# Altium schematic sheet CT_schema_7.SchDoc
size 277 x 170 mm
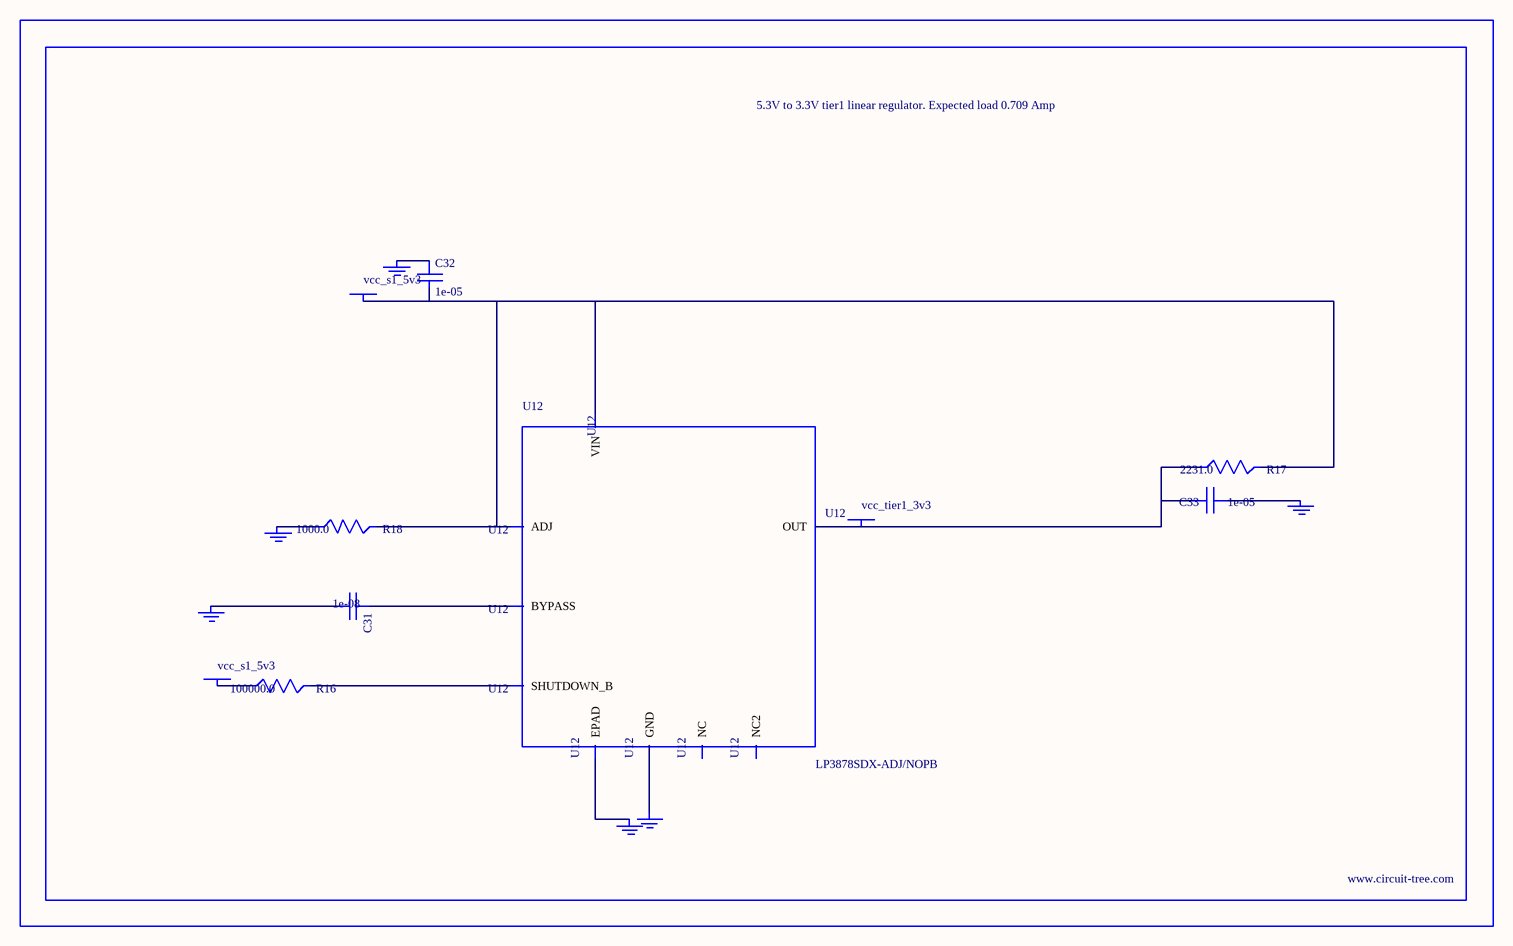
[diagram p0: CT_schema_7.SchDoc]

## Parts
BORDER6  (no value)
C31  1e-08  [C0402]
C32  1e-05  [C1206]
C33  1e-05  [C1210]
GND_INSTANCE_6_0  (no value)
GND_INSTANCE_6_1  (no value)
GND_INSTANCE_6_2  (no value)
GND_INSTANCE_6_3  (no value)
GND_INSTANCE_6_4  (no value)
GND_INSTANCE_6_5  (no value)
POWER_INSTANCE_6_0  vcc_s1_5v3
POWER_INSTANCE_6_1  vcc_s1_5v3
POWER_INSTANCE_6_2  vcc_tier1_3v3
R16  100000.0  [R0603]
R17  2231.0  [R0603]
R18  1000.0  [R0603]
U12  LP3878SDX-ADJ/NOPB  [WSON-8]

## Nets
NetC31_1: C31.1 U12.1(BYPASS)
NetC31_2: C31.2 GND_INSTANCE_6_0.0(GND)
NetC32_1: C32.1 GND_INSTANCE_6_1.0(GND)
NetC32_2: C32.2 POWER_INSTANCE_6_0.0(PWR) R17.2 R18.2 U12.4(VIN) U12.6(ADJ)
NetC33_1: C33.1 GND_INSTANCE_6_2.0(GND)
NetC33_2: C33.2 POWER_INSTANCE_6_2.0(PWR) R17.1 U12.5(OUT)
NetGND_INSTANCE_6_3_0: GND_INSTANCE_6_3.0(GND) R18.1
NetGND_INSTANCE_6_4_0: GND_INSTANCE_6_4.0(GND) U12.PAD(EPAD)
NetGND_INSTANCE_6_5_0: GND_INSTANCE_6_5.0(GND) U12.3(GND)
NetPOWER_INSTANCE_6_1_0: POWER_INSTANCE_6_1.0(PWR) R16.1
NetR16_2: R16.2 U12.8(SHUTDOWN_B)

Not connected (* = marked no-connect by the designer): U12 2(NC) 7(NC2)

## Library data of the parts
BORDER6 = BORDER_PAGE6
C31 = C0402C103K3RAC
C32 = C1206C106K3RACTU
C33 = GRM32DR61E106MA12L
GND_INSTANCE_6_0-GND_INSTANCE_6_5 = GND
POWER_INSTANCE_6_0-POWER_INSTANCE_6_2 = PWR
R16 = RC0603JR-07100KL
R17 = R17
R18 = RC0603JR-071KL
